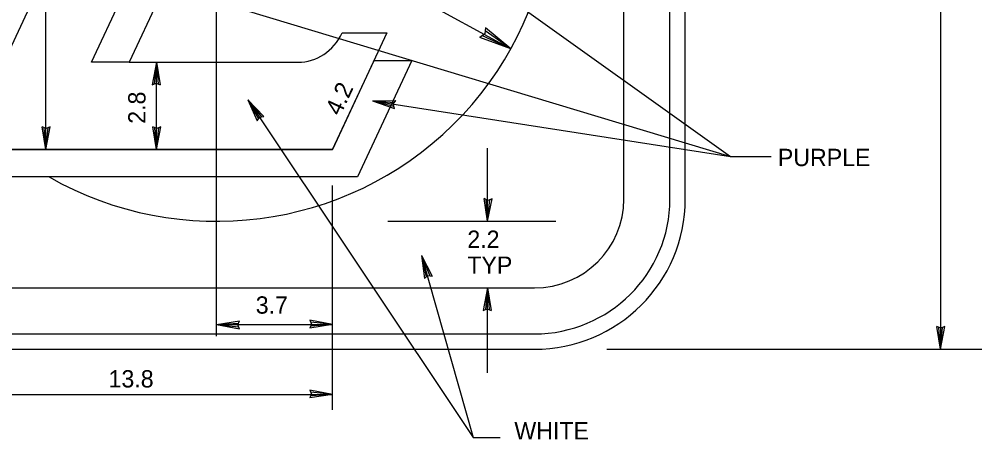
# Model space of a CAD drawing. Extents: x 10268197 to 10269179, y 2141503 to 2142677.
# Drawn here: x 10268695.42 to 10268734.62, y 2141994.18 to 2142011.21 of the extents above; entities that cross this region are included whole.
import ezdxf

# ---------------------------------------------------------------- set-up
doc = ezdxf.new("R2010")
doc.units = 0
for name, color, linetype in [('1', 7, 'Continuous'), ('Default', 7, 'Continuous'), ('TextMisc', 7, 'Continuous'), ('TextShtNo', 7, 'Continuous')]:
    doc.layers.add(name, color=color, linetype=linetype)

msp = doc.modelspace()

# ---------------------------------------------------------------- linework, layer by layer
at = {"layer": '1'}
for p, q in [((10268709.921, 2142015.962), (10268724.389, 2142005.619)), ((10268703.757, 2142011.836), (10268724.389, 2142005.619)), ((10268709.808, 2142007.885), (10268724.389, 2142005.619)), ((10268724.389, 2142005.619), (10268726.041, 2142005.619))]:
    msp.add_line(p, q, dxfattribs=at)
at = {"layer": 'Default'}
for p, q in [((10268732.934, 2142035.28), (10268732.934, 2141997.78)), ((10268720.046, 2142003.891), (10268720.046, 2142029.168)), ((10268696.498, 2142005.913), (10268696.498, 2142027.195)), ((10268694.844, 2142009.556), (10268701.361, 2142023.642)), ((10268703.457, 2141998.311), (10268703.457, 2142016.53)), ((10268703.457, 2142016.53), (10268715.441, 2142010.012)), ((10268698.359, 2142009.459), (10268701.048, 2142015.222)), ((10268702.061, 2142014.103), (10268699.894, 2142009.459)), ((10268714.403, 2142010.866), (10268714.375, 2142010.615)), ((10268715.441, 2142010.012), (10268714.403, 2142010.866)), ((10268710.391, 2142010.655), (10268708.18, 2142005.913)), ((10268708.569, 2142010.655), (10268710.391, 2142010.655)), ((10268714.375, 2142010.615), (10268714.172, 2142010.464)), ((10268715.441, 2142010.012), (10268714.28, 2142010.543)), ((10268715.441, 2142010.012), (10268714.389, 2142010.734)), ((10268715.441, 2142010.012), (10268714.172, 2142010.464)), ((10268699.894, 2142009.459), (10268698.359, 2142009.459)), ((10268699.894, 2142009.459), (10268706.767, 2142009.459)), ((10268701.009, 2142009.459), (10268700.83, 2142008.541)), ((10268701.009, 2142009.459), (10268700.916, 2142008.577)), ((10268701.009, 2142005.913), (10268701.009, 2142009.459)), ((10268701.009, 2142009.459), (10268701.157, 2142008.536)), ((10268701.009, 2142009.459), (10268701.072, 2142008.575)), ((10268711.403, 2142009.533), (10268709.192, 2142004.792)), ((10268709.869, 2142009.533), (10268711.403, 2142009.533)), ((10268700.83, 2142008.541), (10268700.994, 2142008.609)), ((10268700.994, 2142008.609), (10268701.157, 2142008.536)), ((10268704.724, 2142007.932), (10268705.38, 2142007.26)), ((10268704.724, 2142007.932), (10268705.11, 2142007.079)), ((10268704.724, 2142007.932), (10268705.161, 2142007.156)), ((10268704.724, 2142007.932), (10268705.289, 2142007.244)), ((10268704.725, 2142007.933), (10268713.9, 2141994.188)), ((10268709.808, 2142007.885), (10268710.749, 2142007.903)), ((10268709.808, 2142007.885), (10268710.697, 2142007.582)), ((10268709.808, 2142007.885), (10268710.674, 2142007.672)), ((10268709.808, 2142007.885), (10268710.698, 2142007.825)), ((10268710.653, 2142007.754), (10268710.749, 2142007.903)), ((10268710.697, 2142007.582), (10268710.653, 2142007.754)), ((10268705.11, 2142007.079), (10268705.206, 2142007.228)), ((10268705.206, 2142007.228), (10268705.38, 2142007.26)), ((10268696.498, 2142005.913), (10268696.351, 2142006.837)), ((10268696.513, 2142006.764), (10268696.351, 2142006.837)), ((10268696.498, 2142005.913), (10268696.436, 2142006.798)), ((10268696.498, 2142005.913), (10268696.678, 2142006.832)), ((10268696.498, 2142005.913), (10268696.591, 2142006.796)), ((10268696.678, 2142006.832), (10268696.513, 2142006.764)), ((10268701.009, 2142005.913), (10268700.862, 2142006.837)), ((10268701.023, 2142006.764), (10268700.862, 2142006.837)), ((10268701.009, 2142005.913), (10268700.946, 2142006.798)), ((10268701.009, 2142005.913), (10268701.189, 2142006.832)), ((10268701.009, 2142005.913), (10268701.102, 2142006.796)), ((10268701.189, 2142006.832), (10268701.023, 2142006.764)), ((10268708.18, 2142005.913), (10268691.776, 2142005.913)), ((10268714.494, 2142002.988), (10268714.494, 2142005.966)), ((10268709.192, 2142004.792), (10268691.254, 2142004.792)), ((10268708.18, 2141995.31), (10268708.18, 2142004.443)), ((10268714.494, 2142002.988), (10268714.347, 2142003.911)), ((10268714.508, 2142003.838), (10268714.347, 2142003.911)), ((10268714.494, 2142002.988), (10268714.432, 2142003.873)), ((10268714.494, 2142002.988), (10268714.673, 2142003.906)), ((10268714.494, 2142002.988), (10268714.587, 2142003.871)), ((10268714.673, 2142003.906), (10268714.508, 2142003.838)), ((10268710.436, 2142002.988), (10268717.271, 2142002.988)), ((10268711.804, 2142001.589), (10268713.9, 2141994.188)), ((10268711.804, 2142001.589), (10268712.23, 2142000.754)), ((10268711.804, 2142001.589), (10268711.918, 2142000.66)), ((10268711.804, 2142001.589), (10268711.989, 2142000.72)), ((10268711.804, 2142001.589), (10268712.137, 2142000.765)), ((10268711.918, 2142000.66), (10268712.053, 2142000.775)), ((10268712.053, 2142000.775), (10268712.23, 2142000.754)), ((10268679.942, 2142000.28), (10268716.4, 2142000.28)), ((10268714.494, 2142000.28), (10268714.315, 2141999.361)), ((10268714.494, 2142000.28), (10268714.401, 2141999.397)), ((10268714.494, 2141996.823), (10268714.494, 2142000.28)), ((10268714.494, 2142000.28), (10268714.641, 2141999.356)), ((10268714.494, 2142000.28), (10268714.557, 2141999.395)), ((10268714.315, 2141999.361), (10268714.479, 2141999.429)), ((10268714.479, 2141999.429), (10268714.641, 2141999.356)), ((10268703.457, 2141998.783), (10268704.39, 2141998.929)), ((10268703.457, 2141998.783), (10268704.35, 2141998.845)), ((10268703.457, 2141998.783), (10268708.18, 2141998.783)), ((10268703.457, 2141998.783), (10268704.385, 2141998.605)), ((10268703.457, 2141998.783), (10268704.349, 2141998.691)), ((10268704.316, 2141998.768), (10268704.39, 2141998.929)), ((10268704.385, 2141998.605), (10268704.316, 2141998.768)), ((10268707.322, 2141998.798), (10268707.248, 2141998.637)), ((10268708.18, 2141998.783), (10268707.248, 2141998.637)), ((10268708.18, 2141998.783), (10268707.253, 2141998.961)), ((10268707.253, 2141998.961), (10268707.322, 2141998.798)), ((10268708.18, 2141998.783), (10268707.287, 2141998.72)), ((10268708.18, 2141998.783), (10268707.289, 2141998.875)), ((10268732.934, 2141997.78), (10268732.787, 2141998.703)), ((10268732.948, 2141998.63), (10268732.787, 2141998.703)), ((10268732.934, 2141997.78), (10268732.872, 2141998.665)), ((10268732.934, 2141997.78), (10268733.113, 2141998.698)), ((10268732.934, 2141997.78), (10268733.027, 2141998.663)), ((10268733.113, 2141998.698), (10268732.948, 2141998.63)), ((10268719.344, 2141997.78), (10268734.621, 2141997.78)), ((10268708.18, 2141995.941), (10268707.253, 2141996.118)), ((10268707.253, 2141996.118), (10268707.322, 2141995.955)), ((10268708.18, 2141995.941), (10268707.289, 2141996.032)), ((10268690.863, 2141995.941), (10268708.18, 2141995.941)), ((10268707.322, 2141995.955), (10268707.248, 2141995.795)), ((10268708.18, 2141995.941), (10268707.248, 2141995.795)), ((10268708.18, 2141995.941), (10268707.287, 2141995.878)), ((10268713.9, 2141994.188), (10268715.004, 2141994.188))]:
    msp.add_line(p, q, dxfattribs=at)
for centre, major_axis, ratio, start_param, end_param in [((10268703.457, 2142016.529), (13.672, 0), 0.990479, 0.906904, 3.809231), ((10268703.457, 2142016.529), (13.672, 0), 0.990479, 4.190341, 6.796736), ((10268706.767, 2142011.676), (0, 2.217), 0.915383, 3.141593, 4.233038), ((10268716.399, 2142003.89), (3.646, 0), 0.990479, 4.712389, 6.283185)]:
    msp.add_ellipse(centre, major_axis=major_axis, ratio=ratio, start_param=start_param, end_param=end_param, dxfattribs=at)
at = {"layer": 'TextMisc'}
for p, q in [((10268721.921, 2142003.891), (10268721.921, 2142029.168)), ((10268722.546, 2142003.891), (10268722.546, 2142029.168)), ((10268679.942, 2141998.405), (10268716.4, 2141998.405)), ((10268679.942, 2141997.78), (10268716.4, 2141997.78))]:
    msp.add_line(p, q, dxfattribs=at)
for major_axis, ratio in [((5.521, 0), 0.993713), ((6.146, 0), 0.994352)]:
    msp.add_ellipse((10268716.399, 2142003.89), major_axis=major_axis, ratio=ratio, start_param=4.712389, end_param=6.283185, dxfattribs=at)
at = {"layer": 'TextShtNo'}
for p, q in [((10268698.359, 2142009.459), (10268701.048, 2142015.222)), ((10268702.061, 2142014.103), (10268699.894, 2142009.459)), ((10268699.894, 2142009.459), (10268698.359, 2142009.459)), ((10268708.18, 2142005.913), (10268709.869, 2142009.533)), ((10268711.403, 2142009.533), (10268709.192, 2142004.792)), ((10268709.869, 2142009.533), (10268711.403, 2142009.533)), ((10268691.776, 2142005.913), (10268708.18, 2142005.913)), ((10268709.192, 2142004.792), (10268691.254, 2142004.792))]:
    msp.add_line(p, q, dxfattribs=at)

# ---------------------------------------------------------------- texts
at = {"layer": '1'}
for s, rotation, p in [('4.2', 64.85, (10268708.49, 2142007.243)), ('2.8', 90, (10268700.559, 2142006.957))]:
    msp.add_text(s, height=0.7047, rotation=rotation, dxfattribs=at).set_placement(p)
for s, p in [('PURPLE', (10268726.317, 2142005.234)), ('2.2', (10268713.668, 2142001.906)), ('TYP', (10268713.668, 2142000.849)), ('3.7', (10268705.05, 2141999.227)), ('13.8', (10268699.056, 2141996.223)), ('WHITE', (10268715.584, 2141994.107))]:
    msp.add_text(s, height=0.7047, dxfattribs=at).set_placement(p)

doc.saveas('drawing.dxf')
